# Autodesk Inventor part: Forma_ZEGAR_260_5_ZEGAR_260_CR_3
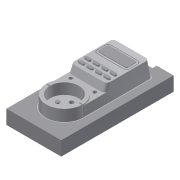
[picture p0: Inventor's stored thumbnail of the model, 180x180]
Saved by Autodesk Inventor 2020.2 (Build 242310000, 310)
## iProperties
Created: 2015-01
Part Number: Forma_ZEGAR_260_5_ZEGAR_260_CR_3
Material: Ogólny
Document SubType Name: Modeling
Designer: F.Stasiak
Density: 1 g/cm^3
Appearance: Domyślna
Catalog Web Link: www.expertbooks.pl
Manager: www.cadconsulting.pl
Company: Fabian Stasiak CAD Consulting
Author: F.Stasiak
Subject: Zbiór ćwiczeń. Autodesk Inventor 2020. Kurs Professional
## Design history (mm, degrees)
node "Forma_ZEGAR_260_4_ZEGAR_260_CR_Base"
feature "Bryła1::Forma_ZEGAR_260_4_ZEGAR_260_CR_Base"
tag "Bryła wyprowadzona1"
node "Bryła1"
feature "Forma_ZEGAR_260_4_ZEGAR_260_CR_Base_Bodies"
